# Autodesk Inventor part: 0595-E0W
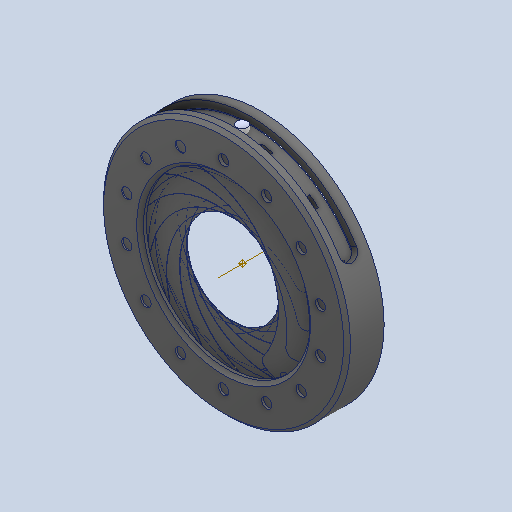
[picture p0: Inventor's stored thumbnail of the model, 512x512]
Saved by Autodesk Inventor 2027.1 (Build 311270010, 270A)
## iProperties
Created: 2023-02
Part Number: 0595-E0W
Material: Generic
Description: STEP AP214
Document SubType Name: Modeling
Designer: dunge
Density: 1 g/cm^3
Appearance: Default
Sending System: SolidWorks 2022
Preprocessor: SwSTEP 2.0
Title: 0595-E0W.STEP
Revision Number: ANY
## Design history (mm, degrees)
feature "700-370 Outer Ring-1-solid1"
feature "700-370 Inner Ring-1-solid1"
feature "700-370 Blade-1-solid1"
feature "700-370 Blade-2-solid1"
feature "700-370 Blade-3-solid1"
feature "700-370 Blade-4-solid1"
feature "700-370 Blade-5-solid1"
feature "700-370 Blade-6-solid1"
feature "700-198 Lever-1-solid1"
feature "700-370 Blade-7-solid1"
feature "700-370 Blade-8-solid1"
feature "700-370 Blade-9-solid1"
feature "700-370 Blade-10-solid1"
feature "700-370 Blade-11-solid1"
feature "700-370 Blade-12-solid1"
feature "700-370 Blade-13-solid1"
feature "700-370 Blade-14-solid1"
sketch "Sketch1"
  geometry: C1 r 1.755 at (0, 0); 2 further points
  constraints: 1 centre point, 1 coincident
extrude "Extrusion1" cut sketch "Sketch1" distance "d0" = 25.4; taper "d1" = 0 deg
workpoint "Work Point1"
  workaxis "Work Axis1"
body "Solid1"
body "Solid2"
body "Solid3"
body "Solid4"
body "Solid5"
body "Solid6"
body "Solid7"
body "Solid8"
body "Solid9"
body "Solid10"
body "Solid11"
body "Solid12"
body "Solid13"
body "Solid14"
body "Solid15"
body "Solid16"
body "Solid17"
